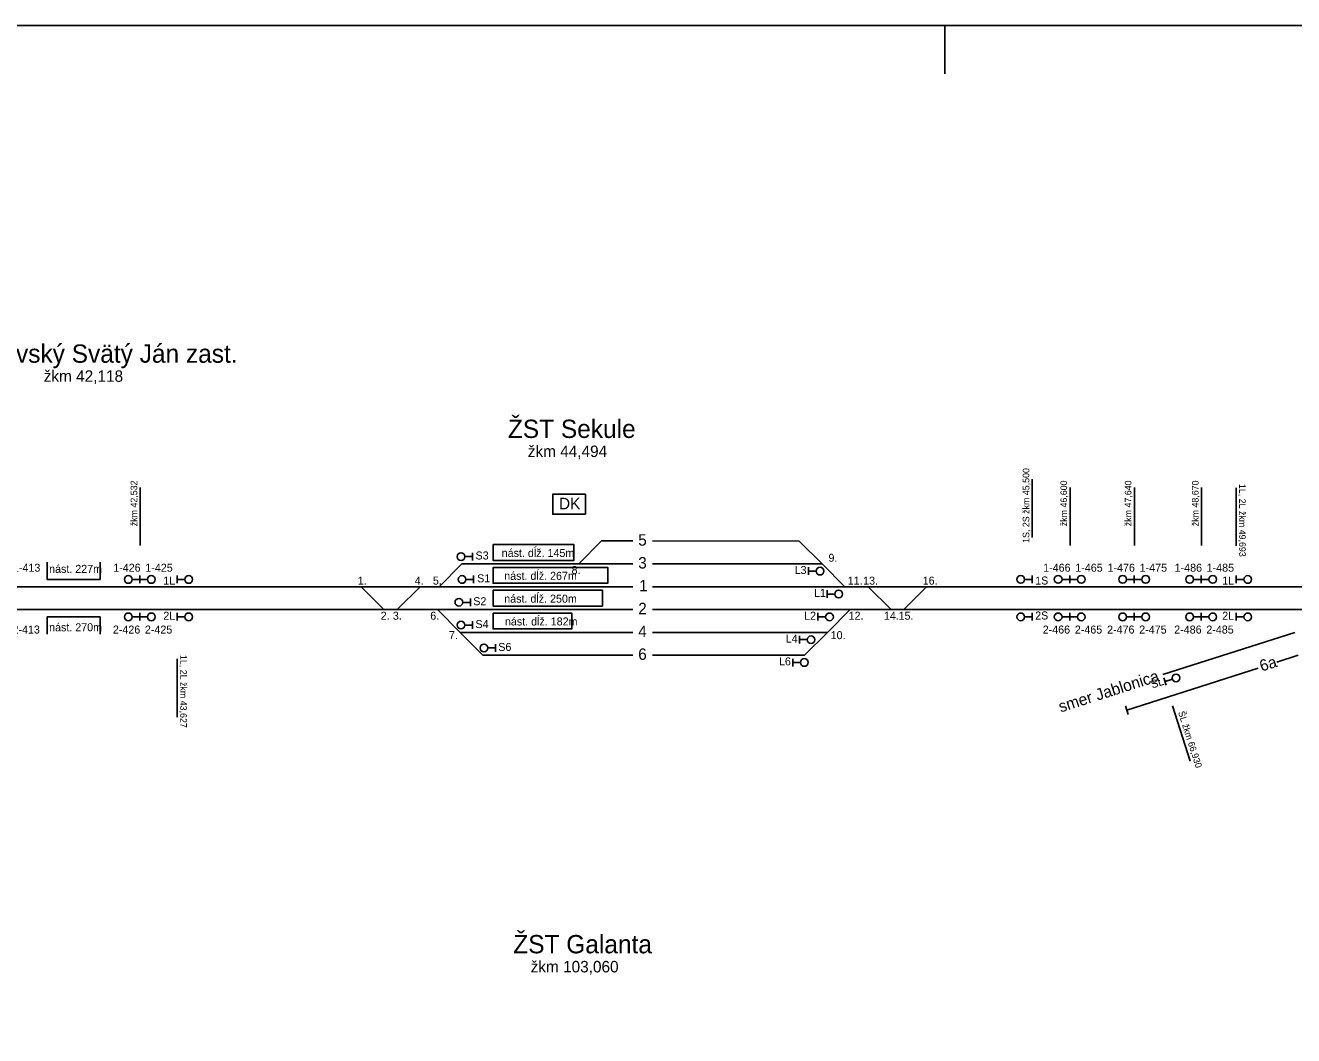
# Model space of a CAD drawing. Extents: x -119 to 851, y -238 to 59.
# Drawn here: x 390.6 to 501.6, y -29.4 to 59 of the extents above; entities that cross this region are included whole.
import ezdxf

# ---------------------------------------------------------------- set-up
doc = ezdxf.new("R2010")
doc.units = 0
for name, color, linetype in [('budova', 7, 'Continuous'), ('Level 2', 7, 'Continuous'), ('nastupistia', 7, 'Continuous'), ('netlač', 7, 'Continuous'), ('popisky navestidla', 7, 'Continuous'), ('popisky stanic a zastavok', 7, 'Continuous'), ('PU_navestidla', 7, 'Continuous'), ('PU_oznacenie navestidiel', 7, 'Continuous'), ('PU_stan_kolaje', 7, 'Continuous'), ('PU_vlecky', 7, 'Continuous')]:
    doc.layers.add(name, color=color, linetype=linetype)

msp = doc.modelspace()

# ---------------------------------------------------------------- linework, layer by layer
at = {"layer": 'budova'}
msp.add_lwpolyline([(439.62, 17.97), (436.76, 17.97), (436.76, 16.22), (439.62, 16.22)], close=True, dxfattribs=at)
at = {"layer": 'Level 2'}
for p, q in [((443.78, 11.89), (428.82, 11.89)), ((460.32, 11.89), (445.5, 11.89)), ((407.29, 9.89), (403.92, 9.89)), ((425.59, 9.89), (407.29, 9.89)), ((443.78, 9.89), (425.59, 9.89)), ((451.38, 9.89), (445.5, 9.89)), ((478.7, 9.89), (451.38, 9.89)), ((511.01, 9.89), (496.54, 9.89)), ((426.59, 7.89), (403.92, 7.89)), ((443.78, 7.89), (426.59, 7.89)), ((450.18, 7.89), (445.5, 7.89)), ((466.38, 7.89), (450.18, 7.89)), ((478.7, 7.89), (466.38, 7.89)), ((511.07, 7.89), (496.54, 7.89)), ((443.78, 5.89), (428.67, 5.89)), ((460.79, 5.89), (445.5, 5.89)), ((430.66, 3.89), (443.78, 3.89)), ((486.85, -0.52), (487.09, -1.28))]:
    msp.add_line(p, q, dxfattribs=at)
at = {"layer": 'nastupistia'}
for points in [[(431.54, 13.57), (438.62, 13.57), (438.62, 12.19), (431.54, 12.19)], [(431.54, 11.58), (441.58, 11.58), (441.58, 10.19), (431.54, 10.19)], [(431.54, 9.58), (441.1, 9.58), (441.1, 8.19), (431.54, 8.19)], [(431.54, 7.58), (438.43, 7.58), (438.43, 6.19), (431.54, 6.19)]]:
    msp.add_lwpolyline(points, close=True, dxfattribs=at)
for points in [[(397.17, 12.03), (397.17, 10.52), (392.53, 10.52), (392.53, 12.03)], [(397.17, 5.75), (397.17, 7.25), (392.53, 7.25), (392.53, 5.75)]]:
    msp.add_lwpolyline(points, dxfattribs=at)
at = {"layer": 'netlač'}
for p, q in [((441.02, 13.89), (443.78, 13.89)), ((445.5, 13.89), (458.32, 13.88)), ((350.14, 9.89), (403.92, 9.89)), ((478.7, 9.89), (496.54, 9.89)), ((350.14, 7.89), (403.92, 7.89)), ((478.7, 7.89), (496.54, 7.89)), ((501.66, 5.89), (490.13, 2.21)), ((458.79, 3.89), (445.5, 3.89)), ((501.97, 3.89), (500.09, 3.29)), ((498.45, 2.77), (486.97, -0.9))]:
    msp.add_line(p, q, dxfattribs=at)
at = {"layer": 'popisky navestidla'}
for p, q in [((471.05, 58.99), (471.05, 54.76)), ((478.71, 14.2), (478.71, 19.29)), ((400.68, 13.49), (400.68, 18.58)), ((482.01, 13.49), (482.01, 18.58)), ((487.65, 13.49), (487.65, 18.58)), ((493.51, 13.49), (493.51, 18.58)), ((496.54, 18.54), (496.54, 13.45)), ((403.92, 3.58), (403.92, -1.51)), ((490.98, -0.52), (492.53, -5.37))]:
    msp.add_line(p, q, dxfattribs=at)
msp.add_lwpolyline([(-118.95, -238.01), (851.05, -238.01), (851.05, 58.99), (-118.95, 58.99)], close=True, dxfattribs=at)
at = {"layer": 'PU_navestidla'}
for p, q in [((429.75, 12.52), (429.08, 12.52)), ((429.75, 12.86), (429.75, 12.19)), ((459.13, 10.92), (459.13, 11.59)), ((459.13, 11.25), (459.8, 11.25)), ((400.65, 10.52), (399.97, 10.52)), ((400.65, 10.86), (400.65, 10.19)), ((400.65, 10.86), (400.65, 10.19)), ((400.65, 10.52), (401.32, 10.52)), ((403.92, 10.86), (403.92, 10.19)), ((403.92, 10.52), (404.59, 10.52)), ((429.84, 10.52), (429.17, 10.52)), ((429.84, 10.86), (429.84, 10.19)), ((478.71, 10.52), (478.04, 10.52)), ((478.71, 10.86), (478.71, 10.19)), ((481.98, 10.52), (481.31, 10.52)), ((481.98, 10.86), (481.98, 10.19)), ((481.98, 10.86), (481.98, 10.19)), ((481.98, 10.52), (482.65, 10.52)), ((487.61, 10.52), (486.94, 10.52)), ((487.61, 10.86), (487.61, 10.19)), ((487.61, 10.86), (487.61, 10.19)), ((487.61, 10.52), (488.29, 10.52)), ((493.48, 10.52), (492.81, 10.52)), ((493.48, 10.86), (493.48, 10.19)), ((493.48, 10.86), (493.48, 10.19)), ((493.48, 10.52), (494.15, 10.52)), ((496.54, 10.86), (496.54, 10.19)), ((496.54, 10.52), (497.21, 10.52)), ((460.77, 8.92), (460.77, 9.59)), ((460.77, 9.25), (461.44, 9.25)), ((429.56, 8.52), (428.88, 8.52)), ((429.56, 8.86), (429.56, 8.19)), ((400.65, 7.25), (399.97, 7.25)), ((400.65, 6.92), (400.65, 7.59)), ((400.65, 6.92), (400.65, 7.59)), ((400.65, 7.25), (401.32, 7.25)), ((403.92, 6.92), (403.92, 7.59)), ((403.92, 7.25), (404.59, 7.25)), ((429.75, 6.86), (429.75, 6.19)), ((459.96, 6.92), (459.96, 7.59)), ((459.96, 7.25), (460.63, 7.25)), ((478.71, 7.25), (478.04, 7.25)), ((478.71, 6.92), (478.71, 7.59)), ((481.98, 7.26), (481.31, 7.26)), ((481.98, 6.92), (481.98, 7.59)), ((481.98, 6.92), (481.98, 7.59)), ((481.98, 7.26), (482.65, 7.26)), ((487.61, 7.26), (486.94, 7.26)), ((487.61, 6.92), (487.61, 7.59)), ((487.61, 6.92), (487.61, 7.59)), ((487.61, 7.26), (488.29, 7.26)), ((493.48, 7.26), (492.81, 7.26)), ((493.48, 6.92), (493.48, 7.59)), ((493.48, 6.92), (493.48, 7.59)), ((493.48, 7.26), (494.15, 7.26)), ((496.54, 6.92), (496.54, 7.59)), ((496.54, 7.25), (497.21, 7.25)), ((429.75, 6.53), (429.08, 6.53)), ((458.35, 4.92), (458.35, 5.59)), ((431.75, 4.53), (431.08, 4.53)), ((431.75, 4.86), (431.75, 4.19)), ((458.35, 5.26), (459.02, 5.26)), ((457.76, 2.92), (457.76, 3.59)), ((457.76, 3.26), (458.43, 3.26)), ((490.42, 1.28), (490.22, 1.92)), ((490.32, 1.6), (490.96, 1.81))]:
    msp.add_line(p, q, dxfattribs=at)
for centre in [(428.74, 12.52), (460.14, 11.25), (399.64, 10.52), (401.65, 10.52), (404.92, 10.52), (428.83, 10.52), (477.7, 10.53), (480.97, 10.53), (482.99, 10.53), (486.61, 10.53), (488.62, 10.53), (492.47, 10.53), (494.49, 10.53), (497.55, 10.52), (461.77, 9.25), (428.55, 8.53), (399.64, 7.25), (401.65, 7.25), (404.92, 7.25), (428.74, 6.53), (460.97, 7.25), (477.7, 7.25), (480.97, 7.25), (482.99, 7.25), (486.61, 7.25), (488.62, 7.25), (492.47, 7.25), (494.49, 7.25), (497.55, 7.25), (459.36, 5.25), (430.74, 4.53), (458.77, 3.26), (491.28, 1.91)]:
    msp.add_circle(centre, 0.336, dxfattribs=at)
at = {"layer": 'PU_stan_kolaje'}
for points in [[(439.03, 11.89), (441.02, 13.89)], [(460.32, 11.89), (458.32, 13.88)], [(426.82, 9.89), (428.82, 11.89)], [(462.32, 9.89), (460.32, 11.89)], [(422, 7.89), (420, 9.89)], [(423.16, 7.89), (425.16, 9.89)], [(466.36, 7.89), (464.36, 9.89)], [(467.46, 7.89), (469.46, 9.89)], [(428.67, 5.89), (426.67, 7.89)], [(460.79, 5.89), (462.79, 7.89)], [(430.66, 3.89), (428.67, 5.89)], [(458.79, 3.89), (460.79, 5.89)]]:
    msp.add_lwpolyline(points, dxfattribs=at)

# ---------------------------------------------------------------- texts
at = {"layer": 'budova'}
msp.add_text('DK', height=1.004, dxfattribs=at).set_placement((437.31, 16.66))
at = {"layer": 'nastupistia'}
for s, p in [('nást. dĺž. 145m', (432.3, 12.49)), ('nást. 227m', (392.71, 11.1)), ('nást. dĺž. 267m', (432.52, 10.49)), ('nást. dĺž. 250m', (432.52, 8.49)), ('nást. 270m', (392.71, 5.99)), ('nást. dĺž. 182m', (432.58, 6.5))]:
    msp.add_text(s, height=0.7, dxfattribs=at).set_placement(p)
at = {"layer": 'popisky navestidla'}
for s, height, rotation, p in [('1S, 2S žkm 45,500', 0.5793, 90, (478.45, 13.72)), ('žkm 42,532', 0.579, 90, (400.42, 15.18)), ('žkm 46,600', 0.579, 90, (481.75, 15.18)), ('žkm 47,640', 0.579, 90, (487.38, 15.18)), ('žkm 48,670', 0.579, 90, (493.25, 15.18)), ('1L, 2L žkm 49,693', 0.5793, 270, (496.8, 18.88)), ('1L, 2L žkm 43,627', 0.5793, 270, (404.18, 3.92)), ('ŠL žkm 66,930', 0.5793, 287.7071, (491.45, -1.1))]:
    msp.add_text(s, height=height, rotation=rotation, dxfattribs=at).set_placement(p)
at = {"layer": 'popisky stanic a zastavok'}
for s, height, p in [('Moravský Svätý Ján zast.', 1.6, (384.94, 29.48)), ('žkm 42,118', 1.004, (392.24, 27.81)), ('ŽST Sekule', 1.6, (432.84, 22.9)), ('žkm 44,494', 1.004, (434.58, 21.23)), ('ŽST Galanta', 1.6, (433.31, -22.18)), ('žkm 103,060', 1.0044, (434.83, -23.85))]:
    msp.add_text(s, height=height, dxfattribs=at).set_placement(p)
at = {"layer": 'PU_oznacenie navestidiel'}
for s, p in [('S3', (430.01, 12.27)), ('9.', (460.88, 12.07)), ('1-413', (389.55, 11.2)), ('1-426', (398.32, 11.2)), ('1-425', (401.13, 11.2)), ('8.', (438.41, 11)), ('L3', (457.92, 11)), ('1-466', (479.66, 11.2)), ('1-465', (482.47, 11.2)), ('1-476', (485.29, 11.2)), ('1-475', (488.1, 11.2)), ('1-486', (491.16, 11.2)), ('1-485', (493.96, 11.2)), ('1L', (402.7, 10.07)), ('1.', (419.71, 10.07)), ('4.', (424.69, 10.07)), ('5.', (426.28, 10.07)), ('S1', (430.15, 10.27)), ('11.', (462.56, 10.07)), ('13.', (463.91, 10.07)), ('16.', (469.12, 10.07)), ('1S', (478.96, 10.08)), ('1L', (495.32, 10.07)), ('S2', (429.81, 8.27)), ('L1', (459.61, 9)), ('2L', (402.7, 7)), ('2.', (421.71, 7)), ('3.', (422.78, 7)), ('6.', (426.05, 7)), ('S4', (430, 6.27)), ('L2', (458.75, 7)), ('12.', (462.64, 7)), ('14.', (465.73, 7)), ('15.', (467.01, 7)), ('2S', (478.96, 7.02)), ('2L', (495.32, 7)), ('2-413', (389.51, 5.79)), ('2-426', (398.29, 5.79)), ('2-425', (401.09, 5.79)), ('7.', (427.68, 5.3)), ('L4', (457.14, 5)), ('10.', (461.07, 5.3)), ('2-466', (479.62, 5.79)), ('2-465', (482.43, 5.79)), ('2-476', (485.25, 5.79)), ('2-475', (488.06, 5.79)), ('2-486', (491.12, 5.79)), ('2-485', (493.93, 5.79)), ('S6', (432, 4.27)), ('L6', (456.55, 3.01))]:
    msp.add_text(s, height=0.7, dxfattribs=at).set_placement(p)
msp.add_text('ŠL', height=0.7, rotation=17.7071, dxfattribs=at).set_placement((489.2, 0.98))
at = {"layer": 'PU_stan_kolaje'}
for s, p in [('5', (444.24, 13.48)), ('3', (444.24, 11.48)), ('1', (444.32, 9.48)), ('2', (444.24, 7.48)), ('4', (444.24, 5.49)), ('6', (444.24, 3.49))]:
    msp.add_text(s, height=1, dxfattribs=at).set_placement(p)
msp.add_text('6a', height=1.004, rotation=17.7071, dxfattribs=at).set_placement((498.77, 2.45))
at = {"layer": 'PU_vlecky'}
msp.add_text('smer Jablonica', height=1.015, rotation=17.7071, dxfattribs=at).set_placement((481.19, -1.12))

doc.saveas('drawing.dxf')
